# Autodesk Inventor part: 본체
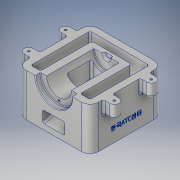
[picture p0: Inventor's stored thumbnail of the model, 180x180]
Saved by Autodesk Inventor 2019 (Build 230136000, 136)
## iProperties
Created: 2022-03
Part Number: 본체
Material: 알루미늄 6061
Document SubType Name: Modeling
Designer: LINE501-1
Density: 2.7 g/cm^3
Appearance: 알루미늄 - 평지
Mass: 1054.87 g
Surface Area: 856.44 cm^2
Volume: 390.692 cm^3
Author: LINE501-1
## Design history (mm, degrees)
sketch "스케치2"
  geometry: L1 (55, 55)-(-55, 55); L2 (-55, 55)-(-55, -55); L3 (-55, -55)-(55, -55); L4 (55, -55)-(55, 55); L5 (55, 55)-(-55, -55); L6 (-55, 55)-(55, -55); L7 (45, 45)-(45, -45); L8 (45, -45)-(-45, -45); L9 (-45, -45)-(-45, 45); L10 (-45, 45)-(-30, 45); L11 (-30, -30)-(-30, 45); L12 (-30, -30)-(30, -30); L13 (30, -30)-(30, 45); L14 (30, 45)-(45, 45); L15 (65, -35)-(55, -35); L16 (65, -21)-(55, -21); A1 r 7 centre (65, -28) between (65, -35) and (65, -21); 1 further point
  constraints: 32 end point, 8 perpendicular, 6 point on line, 3 horizontal, 2 midpoint, 2 parallel, 2 point on circle, 2 tangent, 1 centre point, 1 vertical
  dimensions: "d13" = 110 distance of L3.end L2.end; "d14" = 110 distance of L2.end L1.end; "d15" = 10 distance between parallel lines of L14 L1; "d16" = 10 distance between parallel lines of L10 L1; "d17" = 25 distance between parallel lines of L4 L13; "d18" = 25 distance between parallel lines of L2 L11; "d19" = 14 diameter of A1; "d20" = 65 horizontal distance of A1.centre point (0, 0); "d21" = 27 distance from line of A1.centre L3
extrude "돌출2" new body sketch "스케치2" distance "d24" = 65; taper "d25" = 0 deg
sketch "스케치3"
  geometry: L1 (-45, -45)-(-45, 45); L2 (-45, 45)-(45, 45); L3 (45, 45)-(45, -45); L4 (45, -45)-(30, -45); L5 (30, -45)-(30, 33); L6 (30, 33)-(-30, 33); L7 (-30, 33)-(-30, -45); L8 (-45, -45)-(-30, -45); L9 (-55, -55)-(55, -55) reference; L10 (-55, 55)-(-55, -55) reference; L11 (55, 55)-(-55, 55) reference; L12 (55, -55)-(55, 55) reference; 1 further point
  constraints: 16 end point, 6 perpendicular, 1 parallel, 1 point on line, 1 vertical
  dimensions: "d26" = 10 distance between parallel lines of L9 L8; "d27" = 10 distance between parallel lines of L10 L1; "d28" = 25 distance between parallel lines of L10 L7; "d29" = 10 distance between parallel lines of L11 L2; "d30" = 10 distance between parallel lines of L12 L3; "d31" = 25 distance between parallel lines of L5 L12; "d32" = 22 distance between parallel lines of L11 L6
extrude "돌출3" cut sketch "스케치3" distance "d33" = 65; taper "d34" = 0 deg
sketch "스케치4"
  geometry: L1 (55, 55)-(-55, 55) reference; L2 (-65, 35)-(-55, 35); L3 (-65, 21)-(-55, 21); L4 (-55, 55)-(-55, -55) reference; A1 r 7 centre (-65, 28) between (-65, 35) and (-65, 21); 1 further point
  constraints: 4 end point, 2 horizontal, 2 point on circle, 2 point on line, 2 tangent, 1 centre point
  dimensions: "d36" = 14 diameter of A1; "d37" = 27 distance from line of A1.centre L1; "d38" = 65 horizontal distance of A1.centre point (0, 0)
extrude "돌출4" join sketch "스케치4" distance "d39" = 20; taper "d40" = 0 deg
sketch "스케치5"
  geometry: L1 (65, 55)-(37, 55); L2 (37, 55)-(37, 47); L3 (37, 47)-(46, 47); L4 (46, 47)-(46, -25); L5 (46, -25)-(57.5, -25); L6 (59.809, -29)-(65, -29); L7 (65, -29)-(65, 55); L8 (65, 45)-(65, -33) reference; L9 (57.5, -25)-(59.809, -29); 2 further points
  constraints: 16 end point, 2 perpendicular, 1 midpoint, 1 point on line, 1 vertical
  dimensions: "d44" = 8 distance between parallel lines of L3 L1; "d45" = 72 distance between parallel lines of L5 L3; "d46" = 4 distance between parallel lines of L6 L5; "d47" = 56 diameter of L2 L7; "d48" = 38 diameter of L4 L7; "d49" = 15 diameter of L5.end L7; "d50" = 120 deg angle of L9 L5
revolve "회전1" sketch "스케치5" stored, may be unused: angle "d51" = 90 deg
sketch "스케치7"
  geometry: L1 (8.381, 55)-(28.21, -19); L2 (35.627, 19)-(25.981, 55); L3 (8.381, 55)-(25.981, 55); L4 (5.885, 45)-(0, 45); L5 (28.21, -19)-(55.209, -19); L6 (55.209, -19)-(55.209, 19); L7 (55.209, 19)-(35.627, 19); L8 (0, -45)-(30, -45); L9 (30, -45)-(5.885, 45); L10 (0, -33)-(0, 45) reference; L11 (0, -45)-(0, 45)
  constraints: 20 end point, 2 horizontal, 2 parallel, 2 perpendicular, 1 vertical
  dimensions: "d56" = 36 distance between parallel lines of L7 L3; "d57" = 38 distance between parallel lines of L7 L5; "d61" = 17 distance between parallel lines of L2 L1; "d64" = 15 deg angle of L6 L1; "d87" = 30 distance of L8.start L8.end; "d88" = 75 deg angle of L9 L8; "d90" = 10 distance between parallel lines of L3 L4; "d91" = 55.20924 distance between parallel lines of L10 L6; "d92" = 5 distance between parallel lines of L9 L1
extrude "돌출5" cut sketch "스케치7" stored distance "d66" = 34; taper "d67" = 0 deg
sketch "스케치8"
  geometry: A1 r 7 centre (-65, 28) between (-65, 35) and (-65, 21) reference; A2 r 7 centre (65, 28) between (65, 21) and (65, 35) reference; A3 r 7 centre (65, -28) between (65, -35) and (65, -21) reference; A4 r 7 centre (-65, -28) between (-65, -21) and (-65, -35) reference; 1 further point
hole "구멍1" sketch "스케치8" at (65, 28), (65, -28), (-65, 28), (-65, -28) diameter "d70" = 3.242; stored, may be unused: countersink angle "d74" = 90 deg, drill point angle "d76" = 118 deg; dims "d71" = 9, "d72" = 18, "d73" = 2, "d75" = 11
sketch "스케치9" dims "d77" = 46
  geometry: 4 further points
  constraints: 2 coincident, 1 vertical alignment, 2 other
hole "구멍2" sketch "스케치9" at (0, -23) diameter "d78" = 3.242; stored, may be unused: countersink angle "d82" = 90 deg, drill point angle "d84" = 118 deg; dims "d79" = 9, "d80" = 18, "d81" = 2, "d83" = 11
fillet "모깎기1" dims "d85" = 13, "d86" = 1
extrude "돌출7" cut sketch "스케치7" stored distance "d93" = 80; taper "d94" = 0 deg
fillet "모깎기2" dims "d95" = 3
fillet "모깎기3" dims "d96" = 3
chamfer "모따기1" distance "d97" = 1; stored, may be unused: second distance "d98" = 2, angle "d99" = 45 deg
sketch "스케치10"
  geometry: L1 (-13, 65)-(-13, 0) reference; 2 further points
  constraints: 1 other
  dimensions: "d100" = 55 distance from line of point (42, 20) L1; "d101" = 20 distance of point (42, 20) point (42, 0)
feature "엠보싱1" sketch "스케치10" dims "d102" = 0.5, "d103" = 0
node "솔리드2"
pattern_linear "직사각형 패턴1" dims "d43" = 56
mirror "미러1"
